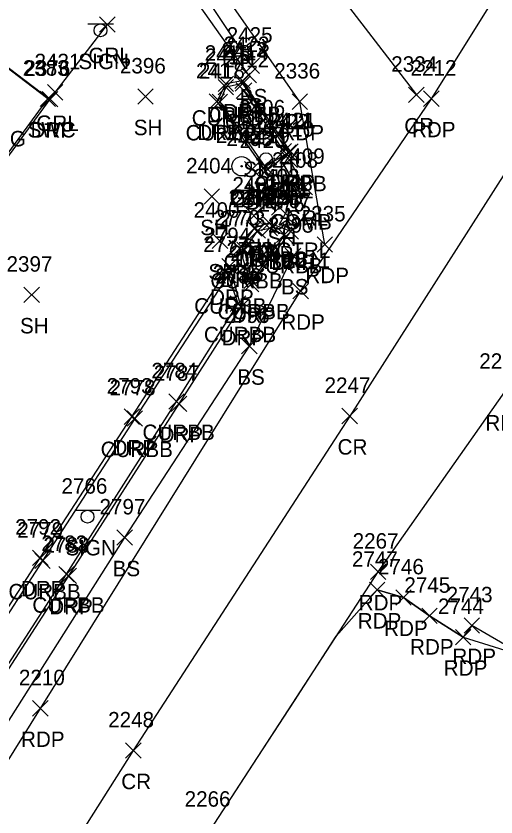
# Model space of a CAD drawing. Extents: x 1638344 to 1639591, y 610835 to 612202.
# Drawn here: x 1639077.4 to 1639139.5, y 611209.2 to 611313 of the extents above; entities that cross this region are included whole.
import ezdxf

# ---------------------------------------------------------------- set-up
doc = ezdxf.new("R2010")
doc.units = 0
for name, color, linetype in [('C_A', 7, 'Continuous'), ('C_I', 7, 'Continuous'), ('CPSM', 7, 'Continuous'), ('L_A', 7, 'Continuous'), ('L_I', 7, 'Continuous'), ('L_TIC', 7, 'Continuous'), ('LELB', 7, 'Continuous'), ('LSOGP', 7, 'Continuous'), ('P_A', 7, 'Continuous'), ('P_I', 7, 'Continuous'), ('P_TIC', 7, 'Continuous'), ('PET', 7, 'Continuous'), ('PRC', 7, 'Continuous'), ('R_A', 7, 'Continuous'), ('R_I', 7, 'Continuous'), ('R_TIC', 7, 'Continuous'), ('RC', 7, 'Continuous'), ('RDP', 7, 'Continuous'), ('RGP', 7, 'Continuous'), ('RGR', 7, 'Continuous'), ('RSW', 7, 'Continuous'), ('S_A', 7, 'Continuous'), ('S_I', 7, 'Continuous'), ('SSGN', 7, 'Continuous'), ('U_A', 7, 'Continuous'), ('U_I', 7, 'Continuous'), ('UP', 7, 'Continuous'), ('UWFH', 7, 'Continuous')]:
    doc.layers.add(name, color=color, linetype=linetype)

msp = doc.modelspace()

# ---------------------------------------------------------------- linework, layer by layer
at = {"layer": 'CPSM'}
for p, q in [((1639111.43, 611285.93), (1639112.68, 611288.09)), ((1639113.93, 611285.93), (1639112.68, 611288.09)), ((1639112.68, 611286.65), (1639112.68, 611288.09)), ((1639111.43, 611285.93), (1639112.68, 611286.65)), ((1639112.68, 611286.65), (1639112.68, 611286.65)), ((1639112.68, 611286.65), (1639113.93, 611285.93)), ((1639111.43, 611285.93), (1639113.93, 611285.93))]:
    msp.add_line(p, q, dxfattribs=at)
at = {"layer": 'L_TIC'}
for points in [[(1639106.91, 611305.54), (1639108.91, 611307.54)], [(1639108.91, 611305.54), (1639106.91, 611307.54)], [(1639106.51, 611304.33), (1639108.51, 611306.33)], [(1639108.51, 611304.33), (1639106.51, 611306.33)], [(1639093.12, 611301.55), (1639095.12, 611303.55)], [(1639095.12, 611301.55), (1639093.12, 611303.55)], [(1639106.96, 611292.15), (1639108.96, 611294.15)], [(1639108.96, 611292.15), (1639106.96, 611294.15)], [(1639101.73, 611288.6), (1639103.73, 611290.6)], [(1639103.73, 611288.6), (1639101.73, 611290.6)], [(1639110.47, 611287.19), (1639112.47, 611289.19)], [(1639112.47, 611287.19), (1639110.47, 611289.19)], [(1639107.18, 611286.13), (1639109.17, 611288.13)], [(1639109.17, 611286.13), (1639107.18, 611288.13)], [(1639102.79, 611282.86), (1639104.79, 611284.86)], [(1639104.79, 611282.86), (1639102.79, 611284.86)], [(1639112.24, 611280.92), (1639114.24, 611282.92)], [(1639114.24, 611280.92), (1639112.24, 611282.92)], [(1639078.38, 611275.87), (1639080.38, 611277.87)], [(1639080.38, 611275.87), (1639078.38, 611277.87)], [(1639106.58, 611269.22), (1639108.58, 611271.22)], [(1639108.58, 611269.22), (1639106.58, 611271.22)], [(1639090.43, 611244.42), (1639092.43, 611246.41)], [(1639092.43, 611244.42), (1639090.43, 611246.41)]]:
    msp.add_lwpolyline(points, dxfattribs=at)
at = {"layer": 'LELB'}
for points in [[(1639107.91, 611306.54), (1639092.17, 611330.06), (1639069.35, 611361.19), (1639057.96, 611376.85)], [(1639107.51, 611305.33), (1639087.16, 611334.08), (1639058.16, 611371.88)], [(1639113.24, 611281.92), (1639107.57, 611270.22), (1639091.43, 611245.42), (1639072.56, 611215.75)]]:
    msp.add_lwpolyline(points, dxfattribs=at)
at = {"layer": 'LSOGP'}
msp.add_lwpolyline([(1639102.56, 611207.56), (1639107.99, 611215.92), (1639113.42, 611224.28), (1639118.85, 611232.64), (1639124.14, 611238.64), (1639127.56, 611237.67), (1639130.93, 611235.27), (1639135.29, 611232.53), (1639143.31, 611230.02), (1639150.22, 611225.99), (1639154.08, 611222.5), (1639157.95, 611219.02), (1639161.82, 611215.53), (1639165.68, 611212.04), (1639169.81, 611207.56)], dxfattribs=at)
at = {"layer": 'P_TIC'}
for points in [[(1639128.23, 611301.77), (1639130.23, 611303.77)], [(1639130.23, 611301.77), (1639128.23, 611303.77)], [(1639113.12, 611300.89), (1639115.12, 611302.89)], [(1639115.12, 611300.89), (1639113.12, 611302.89)], [(1639130.17, 611301.28), (1639132.17, 611303.28)], [(1639132.17, 611301.28), (1639130.17, 611303.28)], [(1639116.36, 611282.38), (1639118.36, 611284.38)], [(1639118.36, 611282.38), (1639116.36, 611284.38)], [(1639113.23, 611276.34), (1639115.23, 611278.34)], [(1639115.23, 611276.34), (1639113.23, 611278.34)], [(1639119.59, 611260.17), (1639121.59, 611262.17)], [(1639121.59, 611260.17), (1639119.59, 611262.17)], [(1639123.27, 611240), (1639125.27, 611241.99)], [(1639125.27, 611240), (1639123.27, 611241.99)], [(1639123.14, 611237.64), (1639125.14, 611239.64)], [(1639125.14, 611237.64), (1639123.14, 611239.64)], [(1639126.57, 611236.67), (1639128.56, 611238.66)], [(1639128.56, 611236.67), (1639126.57, 611238.66)], [(1639129.93, 611234.27), (1639131.93, 611236.27)], [(1639131.93, 611234.27), (1639129.93, 611236.27)], [(1639135.41, 611233.04), (1639137.41, 611235.04)], [(1639137.41, 611233.04), (1639135.41, 611235.04)], [(1639134.29, 611231.53), (1639136.29, 611233.53)], [(1639136.29, 611231.53), (1639134.29, 611233.53)], [(1639079.51, 611222.3), (1639081.51, 611224.3)], [(1639081.51, 611222.3), (1639079.51, 611224.3)], [(1639091.55, 611216.83), (1639093.55, 611218.83)], [(1639093.55, 611216.83), (1639091.55, 611218.83)]]:
    msp.add_lwpolyline(points, dxfattribs=at)
at = {"layer": 'PET'}
for points in [[(1639117.36, 611283.38), (1639114.12, 611301.89), (1639095.51, 611328.5), (1639070.51, 611363.26), (1639041.38, 611404.69), (1639011.58, 611446.4), (1638984.33, 611485.15), (1638954.17, 611527.5), (1638934.33, 611554.77), (1638918.88, 611575.58), (1638893.27, 611605.67), (1638868.12, 611629.84), (1638836.66, 611652.85), (1638812.43, 611667.64)], [(1638854.83, 610853.22), (1638885.37, 610909), (1638902.82, 610937.28), (1638929.33, 610982.56), (1638950.92, 611019.42), (1638971.29, 611051.92), (1639000.04, 611096.97), (1639023.57, 611133.7), (1639039.12, 611159.19), (1639064.62, 611197.79), (1639080.51, 611223.3), (1639114.23, 611277.34), (1639131.17, 611302.28), (1639149.64, 611331.79), (1639176.42, 611372.36), (1639193.48, 611398.88)], [(1638878.4, 610839.82), (1638902.26, 610883.1), (1638925.76, 610925.07), (1638957.26, 610978.12), (1638978.73, 611014.12), (1639004.29, 611055.33), (1639040.97, 611112.29), (1639073.41, 611162.89), (1639102.56, 611207.56), (1639124.27, 611240.99), (1639140.69, 611264.29), (1639156.2, 611287.4), (1639175.63, 611318.1), (1639189.77, 611341.61), (1639219.88, 611389.38)], [(1639410.83, 610892.36), (1639390.46, 610919.54), (1639371.81, 610946.36), (1639349.88, 610975.69), (1639327.19, 611005.39), (1639302.76, 611038.38), (1639275.03, 611075.51), (1639248.84, 611108.82), (1639223.63, 611142.45), (1639205.3, 611166.28), (1639182.19, 611194.12), (1639165.68, 611212.04), (1639150.22, 611225.99), (1639136.41, 611234.04), (1639135.29, 611232.53), (1639130.93, 611235.27), (1639127.56, 611237.67), (1639124.14, 611238.64)]]:
    msp.add_lwpolyline(points, dxfattribs=at)
at = {"layer": 'PRC'}
for points in [[(1638818.79, 611678.84), (1638843.98, 611663.35), (1638876.44, 611637.39), (1638906.24, 611607.19), (1638934.14, 611573.69), (1638965.31, 611531.43), (1638998.82, 611484.34), (1639033.82, 611434.48), (1639068.01, 611386.3), (1639093.94, 611350.49), (1639111.89, 611325.38), (1639129.23, 611302.77)], [(1639222.36, 611418.19), (1639195.34, 611376.27), (1639169.71, 611336.75), (1639147.17, 611302.78), (1639120.59, 611261.17), (1639092.55, 611217.83), (1639063.71, 611172.41), (1639032.46, 611123.7), (1639004.79, 611080.3), (1638977.88, 611037.27), (1638950.44, 610992.13), (1638925.95, 610950.29), (1638900.28, 610905.37), (1638879.75, 610869.2), (1638867.14, 610846.08)]]:
    msp.add_lwpolyline(points, dxfattribs=at)
at = {"layer": 'R_TIC'}
for points in [[(1639088.19, 611310.88), (1639090.19, 611312.87)], [(1639090.19, 611310.88), (1639088.19, 611312.87)], [(1639103.54, 611302.78), (1639105.54, 611304.78)], [(1639105.54, 611302.78), (1639103.54, 611304.78)], [(1639103.55, 611303.2), (1639105.55, 611305.2)], [(1639105.55, 611303.2), (1639103.55, 611305.2)], [(1639105.7, 611303.6), (1639107.7, 611305.6)], [(1639107.7, 611303.6), (1639105.7, 611305.6)], [(1639105.75, 611303.25), (1639107.75, 611305.25)], [(1639107.75, 611303.25), (1639105.75, 611305.25)], [(1639081.44, 611302.1), (1639083.44, 611304.1)], [(1639083.44, 611302.1), (1639081.44, 611304.1)], [(1639105.89, 611302.32), (1639107.89, 611304.32)], [(1639107.89, 611302.32), (1639105.89, 611304.32)], [(1639080.49, 611301.26), (1639082.49, 611303.25)], [(1639082.49, 611301.26), (1639080.49, 611303.25)], [(1639080.75, 611301.23), (1639082.75, 611303.23)], [(1639082.75, 611301.23), (1639080.75, 611303.23)], [(1639102.37, 611300.91), (1639104.37, 611302.91)], [(1639104.37, 611300.91), (1639102.37, 611302.91)], [(1639102.75, 611300.87), (1639104.75, 611302.87)], [(1639104.75, 611300.87), (1639102.75, 611302.87)], [(1639111.05, 611294.48), (1639113.05, 611296.48)], [(1639113.05, 611294.48), (1639111.05, 611296.48)], [(1639111.66, 611294.29), (1639113.66, 611296.29)], [(1639113.66, 611294.29), (1639111.66, 611296.29)], [(1639111.93, 611294.43), (1639113.93, 611296.43)], [(1639113.93, 611294.43), (1639111.93, 611296.43)], [(1639108.59, 611292.51), (1639110.59, 611294.51)], [(1639110.59, 611292.51), (1639108.59, 611294.51)], [(1639111.81, 611293.37), (1639113.81, 611295.36)], [(1639113.81, 611293.37), (1639111.81, 611295.36)], [(1639108.68, 611291.91), (1639110.68, 611293.91)], [(1639110.68, 611291.91), (1639108.68, 611293.91)], [(1639113.75, 611289.84), (1639115.75, 611291.84)], [(1639115.75, 611289.84), (1639113.75, 611291.84)], [(1639109.14, 611285.18), (1639111.14, 611287.18)], [(1639111.14, 611285.18), (1639109.14, 611287.18)], [(1639107.21, 611284.49), (1639109.21, 611286.49)], [(1639109.21, 611284.49), (1639107.21, 611286.49)], [(1639107.68, 611284.2), (1639109.68, 611286.2)], [(1639109.68, 611284.2), (1639107.68, 611286.2)], [(1639109.22, 611284.51), (1639111.22, 611286.51)], [(1639111.22, 611284.51), (1639109.22, 611286.51)], [(1639111.97, 611284.09), (1639113.96, 611286.09)], [(1639113.96, 611284.09), (1639111.97, 611286.09)], [(1639111.12, 611283.66), (1639113.12, 611285.66)], [(1639113.12, 611283.66), (1639111.12, 611285.66)], [(1639105.34, 611281.88), (1639107.34, 611283.88)], [(1639107.34, 611281.88), (1639105.34, 611283.88)], [(1639105.96, 611281.69), (1639107.96, 611283.69)], [(1639107.96, 611281.69), (1639105.96, 611283.69)], [(1639104.01, 611279.57), (1639106.01, 611281.57)], [(1639106.01, 611279.57), (1639104.01, 611281.57)], [(1639103.86, 611278.43), (1639105.86, 611280.43)], [(1639105.86, 611278.43), (1639103.86, 611280.43)], [(1639106.82, 611277.26), (1639108.82, 611279.26)], [(1639108.82, 611277.26), (1639106.82, 611279.26)], [(1639106.88, 611277.7), (1639108.88, 611279.7)], [(1639108.88, 611277.7), (1639106.88, 611279.7)], [(1639105.12, 611274.73), (1639107.12, 611276.73)], [(1639107.12, 611274.73), (1639105.12, 611276.73)], [(1639105.5, 611274.32), (1639107.5, 611276.32)], [(1639107.5, 611274.32), (1639105.5, 611276.32)], [(1639097.16, 611262.06), (1639099.16, 611264.06)], [(1639099.16, 611262.06), (1639097.16, 611264.06)], [(1639097.47, 611261.74), (1639099.47, 611263.74)], [(1639099.47, 611261.74), (1639097.47, 611263.74)], [(1639091.36, 611260.08), (1639093.36, 611262.08)], [(1639093.36, 611260.08), (1639091.36, 611262.08)], [(1639091.74, 611259.85), (1639093.74, 611261.85)], [(1639093.74, 611259.85), (1639091.74, 611261.85)], [(1639079.5, 611241.81), (1639081.5, 611243.81)], [(1639081.5, 611241.81), (1639079.5, 611243.81)], [(1639079.78, 611241.42), (1639081.78, 611243.42)], [(1639081.78, 611241.42), (1639079.78, 611243.42)], [(1639082.89, 611239.69), (1639084.89, 611241.69)], [(1639084.89, 611239.69), (1639082.89, 611241.69)], [(1639083.17, 611239.47), (1639085.17, 611241.47)], [(1639085.17, 611239.47), (1639083.17, 611241.47)]]:
    msp.add_lwpolyline(points, dxfattribs=at)
at = {"layer": 'RC'}
for points in [[(1639106.75, 611304.25), (1639104.54, 611303.78), (1639103.75, 611301.87), (1639109.59, 611293.51), (1639112.66, 611295.29)], [(1639112.66, 611295.29), (1639106.75, 611304.25)], [(1639107.88, 611278.7), (1639106.96, 611282.69), (1639108.68, 611285.2), (1639110.22, 611285.51), (1639112.12, 611284.66)], [(1639112.12, 611284.66), (1639107.88, 611278.7)], [(1639104.86, 611279.43), (1639092.74, 611260.85), (1639080.78, 611242.42), (1639066.66, 611220.66), (1639066.36, 611219.28), (1639069.3, 611218.15), (1639083.89, 611240.69), (1639098.16, 611263.06), (1639106.12, 611275.73)], [(1639106.12, 611275.73), (1639104.86, 611279.43)]]:
    msp.add_lwpolyline(points, dxfattribs=at)
at = {"layer": 'RDP'}
for points in [[(1639050, 611363.21), (1639052.92, 611360.76), (1639053.7, 611361.6), (1639062.63, 611354.26), (1639047.89, 611333.93), (1639066.74, 611319.84), (1639063.67, 611315.97), (1639081.74, 611302.23), (1639062.87, 611276.44), (1639031.25, 611232.69), (1639026.15, 611236.71)], [(1639106.7, 611304.6), (1639104.55, 611304.2), (1639103.37, 611301.91), (1639109.68, 611292.91), (1639112.93, 611295.43)], [(1639112.93, 611295.43), (1639106.7, 611304.6)], [(1639112.96, 611285.09), (1639110.14, 611286.18), (1639108.21, 611285.49), (1639106.33, 611282.88), (1639107.82, 611278.26)], [(1639107.82, 611278.26), (1639112.96, 611285.09)], [(1639106.5, 611275.32), (1639098.47, 611262.74), (1639084.17, 611240.47), (1639069.41, 611217.7), (1639065.99, 611219.02), (1639066.36, 611220.94), (1639080.5, 611242.81), (1639092.36, 611261.08), (1639105.01, 611280.57)], [(1639105.01, 611280.57), (1639106.5, 611275.32)]]:
    msp.add_lwpolyline(points, dxfattribs=at)
at = {"layer": 'RGP'}
msp.add_line((1639106.58, 611293.52), (1639106.58, 611293.52), dxfattribs=at)
for radius in [1.25, 0.0833]:
    msp.add_circle((1639106.58, 611293.52), radius, dxfattribs=at)
at = {"layer": 'RGR'}
for points in [[(1639082.44, 611303.1), (1639089.19, 611311.88)], [(1639112.05, 611295.48), (1639106.89, 611303.32)], [(1639114.75, 611290.84), (1639112.81, 611294.36)]]:
    msp.add_lwpolyline(points, dxfattribs=at)
at = {"layer": 'RSW'}
msp.add_lwpolyline([(1639026.5, 611236.8), (1639031.23, 611233.38), (1639051.47, 611261.19), (1639081.49, 611302.26), (1639063.52, 611315.95), (1639066.44, 611319.95), (1639047.62, 611333.9), (1639054.45, 611343.13), (1639055.18, 611344.17), (1639061.85, 611353.35), (1639049.88, 611363.09)], dxfattribs=at)
at = {"layer": 'SSGN'}
for p, q in [((1639086.65, 611311.96), (1639089.99, 611311.96)), ((1639088.3, 611311.13), (1639088.3, 611311.13)), ((1639108.04, 611297.98), (1639111.37, 611297.98)), ((1639109.68, 611297.14), (1639109.68, 611297.14)), ((1639084.98, 611248.96), (1639088.31, 611248.96)), ((1639086.62, 611248.13), (1639086.62, 611248.13))]:
    msp.add_line(p, q, dxfattribs=at)
for centre in [(1639088.3, 611311.13), (1639109.68, 611297.14), (1639086.62, 611248.13)]:
    msp.add_circle(centre, 0.833, dxfattribs=at)
at = {"layer": 'UP'}
for p, q in [((1639114.12, 611292), (1639113.87, 611291.16)), ((1639113.03, 611289.5), (1639113.03, 611291.16)), ((1639113.03, 611291.16), (1639114.7, 611291.16)), ((1639113.87, 611290.33), (1639113.87, 611290.33)), ((1639114.7, 611291.16), (1639114.7, 611289.5)), ((1639114.7, 611289.5), (1639113.03, 611289.5)), ((1639113.62, 611288.66), (1639113.87, 611289.5))]:
    msp.add_line(p, q, dxfattribs=at)
msp.add_circle((1639113.87, 611290.33), 0.833, dxfattribs=at)
at = {"layer": 'UWFH'}
msp.add_line((1639109.74, 611294.44), (1639109.74, 611294.44), dxfattribs=at)
for centre, radius in [((1639108.74, 611294.44), 0.167), ((1639109.74, 611294.44), 0.833), ((1639110.74, 611294.44), 0.167), ((1639109.74, 611293.44), 0.167)]:
    msp.add_circle(centre, radius, dxfattribs=at)

# ---------------------------------------------------------------- texts
at = {"layer": 'C_A'}
msp.add_text('HVCTRL', height=2, dxfattribs=at).set_placement((1639107.37, 611281.65))
at = {"layer": 'C_I'}
msp.add_text('11', height=2, dxfattribs=at).set_placement((1639112.35, 611289.65))
at = {"layer": 'L_A'}
for s, p in [('BS', (1639106.35, 611301.54)), ('TS', (1639105.92, 611300.33)), ('SH', (1639092.61, 611297.55)), ('BLDG', (1639071.35, 611296.1)), ('SH', (1639106.45, 611288.15)), ('SH', (1639101.22, 611284.6)), ('SH', (1639109.96, 611283.19)), ('SH', (1639106.66, 611282.13)), ('SH', (1639102.28, 611278.86)), ('BS', (1639111.68, 611276.92)), ('SH', (1639077.87, 611271.87)), ('BS', (1639106.02, 611265.22)), ('BS', (1639089.87, 611240.41))]:
    msp.add_text(s, height=2, dxfattribs=at).set_placement(p)
at = {"layer": 'L_I'}
for s, p in [('2425', (1639104.65, 611309.54)), ('2423', (1639104.25, 611308.33)), ('2396', (1639090.81, 611305.55)), ('2403', (1639104.62, 611296.15)), ('2404', (1639099.39, 611292.6)), ('2402', (1639108.13, 611291.19)), ('2401', (1639105.4, 611290.13)), ('2400', (1639100.36, 611286.86)), ('2795', (1639109.98, 611284.92)), ('2397', (1639076.12, 611279.87)), ('2796', (1639104.26, 611273.22)), ('2797', (1639088.17, 611248.42))]:
    msp.add_text(s, height=2, dxfattribs=at).set_placement(p)
at = {"layer": 'P_A'}
for s, p in [('CR', (1639127.66, 611297.77)), ('RDP', (1639111.61, 611296.89)), ('RDP', (1639128.66, 611297.28)), ('RDP', (1639114.85, 611278.38)), ('RDP', (1639111.72, 611272.34)), ('RDP', (1639138.17, 611259.29)), ('CR', (1639119.02, 611256.17)), ('RDP', (1639121.76, 611235.99)), ('RDP', (1639121.63, 611233.64)), ('RDP', (1639125.05, 611232.67)), ('RDP', (1639128.41, 611230.27)), ('RDP', (1639133.9, 611229.04)), ('RDP', (1639132.78, 611227.53)), ('RDP', (1639078, 611218.3)), ('CR', (1639090.99, 611212.83))]:
    msp.add_text(s, height=2, dxfattribs=at).set_placement(p)
at = {"layer": 'P_I'}
for s, p in [('2336', (1639110.81, 611304.89)), ('2334', (1639125.97, 611305.77)), ('2212', (1639128.48, 611305.28)), ('2335', (1639114.11, 611286.38)), ('2211', (1639112.1, 611280.34)), ('2268', (1639137.38, 611267.29)), ('2247', (1639117.33, 611264.17)), ('2267', (1639120.97, 611243.99)), ('2747', (1639120.88, 611241.64)), ('2746', (1639124.25, 611240.66)), ('2745', (1639127.67, 611238.27)), ('2743', (1639133.15, 611237.04)), ('2744', (1639132.03, 611235.53)), ('2210', (1639077.73, 611226.3)), ('2248', (1639089.29, 611220.83)), ('2266', (1639099.2, 611210.56))]:
    msp.add_text(s, height=2, dxfattribs=at).set_placement(p)
at = {"layer": 'R_A'}
for s, p in [('GRL', (1639086.73, 611306.88)), ('CURBB', (1639100.12, 611298.78)), ('DRP', (1639102.04, 611299.2)), ('CURBB', (1639102.33, 611299.25)), ('DRP', (1639104.19, 611299.6)), ('GRL', (1639079.98, 611298.1)), ('GRL', (1639104.43, 611298.32)), ('SWC', (1639078.85, 611297.26)), ('DRP', (1639079.23, 611297.23)), ('CURBB', (1639099.33, 611296.87)), ('DRP', (1639100.85, 611296.91)), ('CURBB', (1639108.25, 611290.29)), ('GRL', (1639109.6, 611290.48)), ('DRP', (1639110.41, 611290.43)), ('GRL', (1639110.36, 611289.36)), ('GP', (1639105.01, 611288.52)), ('CURBB', (1639105.18, 611288.51)), ('DRP', (1639107.17, 611287.91)), ('GRL', (1639112.29, 611285.84)), ('DRP', (1639107.63, 611281.18)), ('CURBB', (1639104.26, 611280.2)), ('DRP', (1639105.7, 611280.49)), ('CURBB', (1639105.8, 611280.51)), ('DRP', (1639110.45, 611280.09)), ('CURBB', (1639107.7, 611279.66)), ('DRP', (1639103.82, 611277.88)), ('CURBB', (1639102.54, 611277.69)), ('DRP', (1639102.5, 611275.57)), ('CURBB', (1639100.44, 611274.43)), ('CURBB', (1639103.46, 611273.7)), ('DRP', (1639105.31, 611273.26)), ('CURBB', (1639101.7, 611270.73)), ('DRP', (1639103.99, 611270.32)), ('CURBB', (1639093.74, 611258.06)), ('DRP', (1639095.96, 611257.74)), ('DRP', (1639089.85, 611256.08)), ('CURBB', (1639088.32, 611255.85)), ('CURBB', (1639076.37, 611237.42)), ('DRP', (1639077.99, 611237.81)), ('CURBB', (1639079.47, 611235.69)), ('DRP', (1639081.66, 611235.47))]:
    msp.add_text(s, height=2, dxfattribs=at).set_placement(p)
at = {"layer": 'R_I'}
for s, p in [('2416', (1639101.8, 611307.2)), ('2413', (1639104.01, 611307.6)), ('2414', (1639104.05, 611307.25)), ('2431', (1639079.75, 611306.1)), ('2415', (1639101.84, 611306.78)), ('2412', (1639104.2, 611306.32)), ('2383', (1639078.23, 611305.26)), ('2376', (1639078.43, 611305.23)), ('2417', (1639100.67, 611304.91)), ('2418', (1639101.05, 611304.87)), ('2422', (1639109.4, 611298.29)), ('2411', (1639109.93, 611298.48)), ('2421', (1639110.23, 611298.43)), ('2405', (1639103.24, 611296.52)), ('2419', (1639106.89, 611296.51)), ('2410', (1639110.03, 611297.36)), ('2420', (1639106.33, 611295.91)), ('2409', (1639111.4, 611293.84)), ('2769', (1639104.89, 611288.49)), ('2768', (1639106.83, 611289.18)), ('2775', (1639106.96, 611288.51)), ('2774', (1639105.42, 611288.2)), ('2776', (1639108.8, 611287.66)), ('2767', (1639109.66, 611288.09)), ('2770', (1639102.99, 611285.88)), ('2773', (1639103.7, 611285.69)), ('2794', (1639101.75, 611283.57)), ('2777', (1639101.6, 611282.43)), ('2772', (1639104.62, 611281.7)), ('2771', (1639105.13, 611281.26)), ('2785', (1639102.86, 611278.73)), ('2786', (1639103.18, 611278.32)), ('2784', (1639094.9, 611266.06)), ('2787', (1639095.21, 611265.74)), ('2793', (1639089.1, 611264.08)), ('2778', (1639089.48, 611263.85)), ('2792', (1639077.24, 611245.81)), ('2779', (1639077.52, 611245.42)), ('2783', (1639080.63, 611243.69)), ('2788', (1639080.91, 611243.47))]:
    msp.add_text(s, height=2, dxfattribs=at).set_placement(p)
at = {"layer": 'S_A'}
for p in [(1639085.44, 611306.11), (1639106.82, 611292.12), (1639083.76, 611243.11)]:
    msp.add_text('SIGN', height=2, dxfattribs=at).set_placement(p)
at = {"layer": 'S_I'}
for s, p in [('2406', (1639106.27, 611300.12)), ('2766', (1639083.24, 611251.11))]:
    msp.add_text(s, height=2, dxfattribs=at).set_placement(p)
at = {"layer": 'U_A'}
for s, p in [('HYD', (1639107.26, 611289.44)), ('COMB', (1639110.25, 611285.33))]:
    msp.add_text(s, height=2, dxfattribs=at).set_placement(p)
at = {"layer": 'U_I'}
for s, p in [('2407', (1639106.4, 611297.44)), ('2408', (1639110.53, 611293.33))]:
    msp.add_text(s, height=2, dxfattribs=at).set_placement(p)

doc.saveas('drawing.dxf')
